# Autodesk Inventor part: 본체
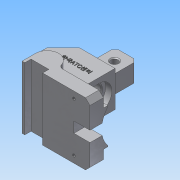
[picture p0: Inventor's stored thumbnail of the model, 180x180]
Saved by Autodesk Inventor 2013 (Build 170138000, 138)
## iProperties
Created: 2016-11
Part Number: 본체
Material: 알루미늄 6061
Document SubType Name: Modeling
Designer: Administrator
Density: 2.71 g/cm^3
Mass: 462.906 g
Surface Area: 317.29 cm^2
Volume: 170.814 cm^3
Author: Administrator
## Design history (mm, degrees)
sketch "스케치1"
  geometry: 1 further point
sketch "스케치2"
  geometry: L1 (-13, 0)-(-13, -15); L2 (13, 0)-(63, 0); L3 (63, 0)-(63, -15); L4 (-13, -15)-(-10, -15); L5 (-10, -15)-(-10, -8); L6 (-10, -8)-(10, -8); L7 (10, -8)-(10, -15); L8 (10, -15)-(63, -15); A1 r 13 centre (0, 0) between (12.488, 3.611) and (-13, 0); A2 r 5 centre (17.292, 5) between (12.488, 3.611) and (17.292, 0); 1 further point
  constraints: 16 end point, 4 perpendicular, 4 point on circle, 3 tangent, 2 centre point, 2 parallel, 1 coincident, 1 horizontal alignment, 1 point on line, 1 vertical
  dimensions: "d0" = 26 diameter of A1; "d1" = 15 distance of L1.start L1.end; "d2" = 10 diameter of A2; "d3" = 63 distance of L2.end point (0, 0); "d5" = 15 distance of L2.end L3.end; "d6" = 3 distance of L1.end L4.end; "d7" = 7 distance of L4.end L5.end; "d8" = 20 distance of L5.end L6.end; "d9" = 7 distance of L6.end L7.end; "d10" = 50 distance of L2.start L2.end
extrude "돌출1" new body sketch "스케치2" distance "d11" = 15; taper "d12" = 0 deg
chamfer "모따기1" distance "d13" = 5; stored, may be unused: second distance "d14" = 2, angle "d15" = 45 deg
node "작업 평면1"
sketch "스케치4"
  geometry: L1 (-13, -15)-(-13, 0) reference; L2 (17.292, 0)-(63, 0) reference; L3 (63, 0)-(63, -15) reference; L4 (63, -15)-(10, -15) reference; L5 (10, -15)-(10, -8) reference; L6 (10, -8)-(-10, -8) reference; L7 (-10, -8)-(-10, -15) reference; L8 (-10, -15)-(-13, -15) reference; A1 r 13 centre (0, 0) between (12.488, 3.611) and (-13, 0) reference; A2 r 5 centre (17.292, 5) between (12.488, 3.611) and (17.292, 0) reference; 1 further point
extrude "돌출2" join sketch "스케치4" distance "d21" = 15; taper "d22" = 0 deg
chamfer "모따기2" distance "d23" = 5; stored, may be unused: second distance "d24" = 2, angle "d25" = 45 deg
sketch "스케치5"
  geometry: L1 (0, 0)-(-10, 0) reference; L2 (0, 15)-(0, 0) reference; L3 (0, 15)-(-10, 15) reference; L4 (0, 15)-(0, 20); L5 (50, 15)-(50, 0) reference; L6 (50, 15)-(40, 15) reference; L7 (40, 0)-(40, 15) reference; L8 (50, 0)-(40, 0) reference; L9 (40, 15)-(40, 20); L10 (-15, 15)-(-15, 0) reference; L11 (0, 20)-(1.106, 20); L12 (40, 20)-(38.894, 20); L13 (14, 0)-(14, 13.627); L14 (26, 0)-(26, 13.627); L15 (0, 0)-(14, 0); L16 (26, 0)-(40, 0); A1 r 29 centre (20, 42) between (1.106, 20) and (14, 13.627); A2 r 29 centre (20, 42) between (26, 13.627) and (38.894, 20)
  constraints: 16 end point, 5 perpendicular, 4 point on circle, 3 parallel, 2 centre point, 1 collinear
  dimensions: "d27" = 5 distance of L2.start L4.end; "d28" = 5 distance of L6.end L9.end; "d29" = 42 distance from line of L1 A1.centre; "d30" = 35 distance from line of L10 A1.centre; "d31" = 6 horizontal distance of A1.centre L13.start; "d32" = 6 distance from line of L14 A1.centre; "d33" = 29 radius of A1; "d34" = 29 radius of A2
extrude "돌출3" join sketch "스케치5" distance "d35" = 18; taper "d36" = 0 deg
sketch "스케치7"
  geometry: L1 (-40, 20)-(-40, 15) reference; L2 (-40, 0)-(-40, 15) reference; L3 (-40, 0)-(-26, 0) reference; L4 (-40, 20)-(-40, 0); L5 (0, 20)-(0, 15) reference; L6 (-40, 20)-(0, 20); L7 (0, 0)-(-40, 0); L8 (0, 20)-(0, 0)
  constraints: 8 end point, 2 collinear, 2 perpendicular, 1 point on line
extrude "돌출4" join sketch "스케치7" distance "d38" = 58; taper "d39" = 0 deg
node "작업 평면6"
sketch "스케치11"
  geometry: L1 (10, 20)-(10, 28) reference; L2 (10, 20)-(50, 20) reference; L3 (50, 28)-(50, 20) reference; L4 (10, 20)-(10, 60); L5 (10, 60)-(50, 60); L6 (50, 60)-(50, 20); L7 (65, 0)-(-5, 0) reference; 1 further point
  constraints: 6 end point, 1 parallel, 1 perpendicular
  dimensions: "d55" = 40 distance of L4.end L5.end; "d56" = 60 distance between parallel lines of L7 L5
extrude "돌출7" join sketch "스케치11" distance "d57" = 58; taper "d58" = 0 deg
sketch "스케치12"
  geometry: L1 (0, 40)-(0, 0) reference; L2 (0, 40)-(-58, 40) reference; L3 (-58, 0)-(-58, 40) reference; L4 (0, 0)-(-58, 0) reference; 1 further point
extrude "돌출8" join sketch "스케치12" distance "d59" = 48; taper "d60" = 0 deg
chamfer "모따기4" distance "d61" = 18; stored, may be unused: second distance "d62" = 2, angle "d63" = 45 deg
chamfer "모따기5" distance "d64" = 4; stored, may be unused: second distance "d65" = 2, angle "d66" = 45 deg
sketch "스케치13"
  geometry: L1 (50, 60)-(10, 60) reference; L2 (-5, 0)-(0, 0) reference; 3 further points
  constraints: 1 midpoint, 1 vertical alignment
  dimensions: "d67" = 42 distance from line of L2 point (30, 42)
hole "구멍1" sketch "스케치13" at (30, 42) diameter "d68" = 20; stored, may be unused: countersink angle "d72" = 90 deg, drill point angle "d74" = 118 deg; dims "d69" = 6, "d70" = 29, "d71" = 7, "d73" = 8
chamfer "모따기7" distance "d78" = 1; stored, may be unused: second distance "d79" = 2, angle "d80" = 45 deg
sketch "스케치14"
  geometry: L1 (20, -7)-(20, 0) reference; L2 (20, 0)-(0, 0) reference; L3 (0, 0)-(0, -7) reference; L4 (20, -7)-(0, -7) reference; 1 further point
extrude "돌출9" cut sketch "스케치14" stored distance "d81" = 48; taper "d82" = 0 deg
node "작업 평면7"
sketch "스케치15"
  geometry: L1 (10, 60)-(50, 60) reference; L2 (20, 60)-(20, 90); L3 (20, 90)-(40, 90); L4 (40, 90)-(40, 60); L5 (65, 0)-(-5, 0) reference; 3 further points
  constraints: 6 end point, 3 perpendicular, 2 midpoint, 2 point on line, 1 vertical alignment
  dimensions: "d84" = 20 distance of L2.end L3.end; "d85" = 90 distance between parallel lines of L5 L3
extrude "돌출10" join sketch "스케치15" distance "d86" = 25; taper "d87" = 0 deg
chamfer "모따기8" distance "d88" = 4; stored, may be unused: second distance "d89" = 2, angle "d90" = 45 deg
sketch "스케치16"
  geometry: L1 (0, 0)-(0, 26) reference; L2 (9, -60)-(57, -60) reference; 2 further points
  dimensions: "d91" = 12.5 distance from line of L1 point (12.5, 17); "d92" = 77 distance from line of L2 point (12.5, 17)
hole "구멍2" sketch "스케치16" at (12.5, 17) diameter "d93" = 8; stored, may be unused: countersink angle "d97" = 90 deg, drill point angle "d99" = 118 deg; dims "d94" = 6, "d95" = 29, "d96" = 7, "d98" = 8
chamfer "모따기9" distance "d100" = 1; stored, may be unused: second distance "d101" = 2, angle "d102" = 45 deg
sketch "스케치17"
  geometry: L1 (45.708, 15)-(45.708, 5) reference; L2 (40.708, 0)-(0, 0) reference; L3 (27.708, 41)-(27.708, 29) reference; L4 (40.708, 70)-(-7.292, 70) reference; 3 further points
  constraints: 1 vertical alignment
  dimensions: "d103" = 18 distance from line of point (27.708, 7.5) L1; "d104" = 7.5 distance from line of L2 point (27.708, 7.5); "d105" = 7.5 distance from line of L4 point (27.708, 62.5)
hole "구멍3" sketch "스케치17" at (27.708, 7.5), (27.708, 62.5) diameter "d106" = 3.242; stored, may be unused: countersink angle "d110" = 90 deg, drill point angle "d112" = 118 deg; dims "d107" = 30, "d108" = 29, "d109" = 7, "d111" = 30
sketch "스케치18"
  geometry: L1 (-32, 45)-(-32, 5) reference; L2 (-32, 45)-(-72, 45) reference; 1 further point
  constraints: 1 other
  dimensions: "d113" = 25 distance from line of L1 point (-57, 27); "d114" = 18 distance from line of point (-57, 27) L2
feature "엠보싱1" sketch "스케치18" dims "d0" = 26, "d1" = 15, "d2" = 10, "d3" = 63, "d5" = 15, "d6" = 3, "d7" = 7, "d8" = 20, "d9" = 7, "d10" = 50, "d115" = 0.5, "d116" = 0
fillet "모깎기1" dims "d117" = 3
node "솔리드1"
node "투영된 루프1"
node "투영된 루프2"
other parameters: "d26" = 58, "d54" = -32, "d83" = -5
